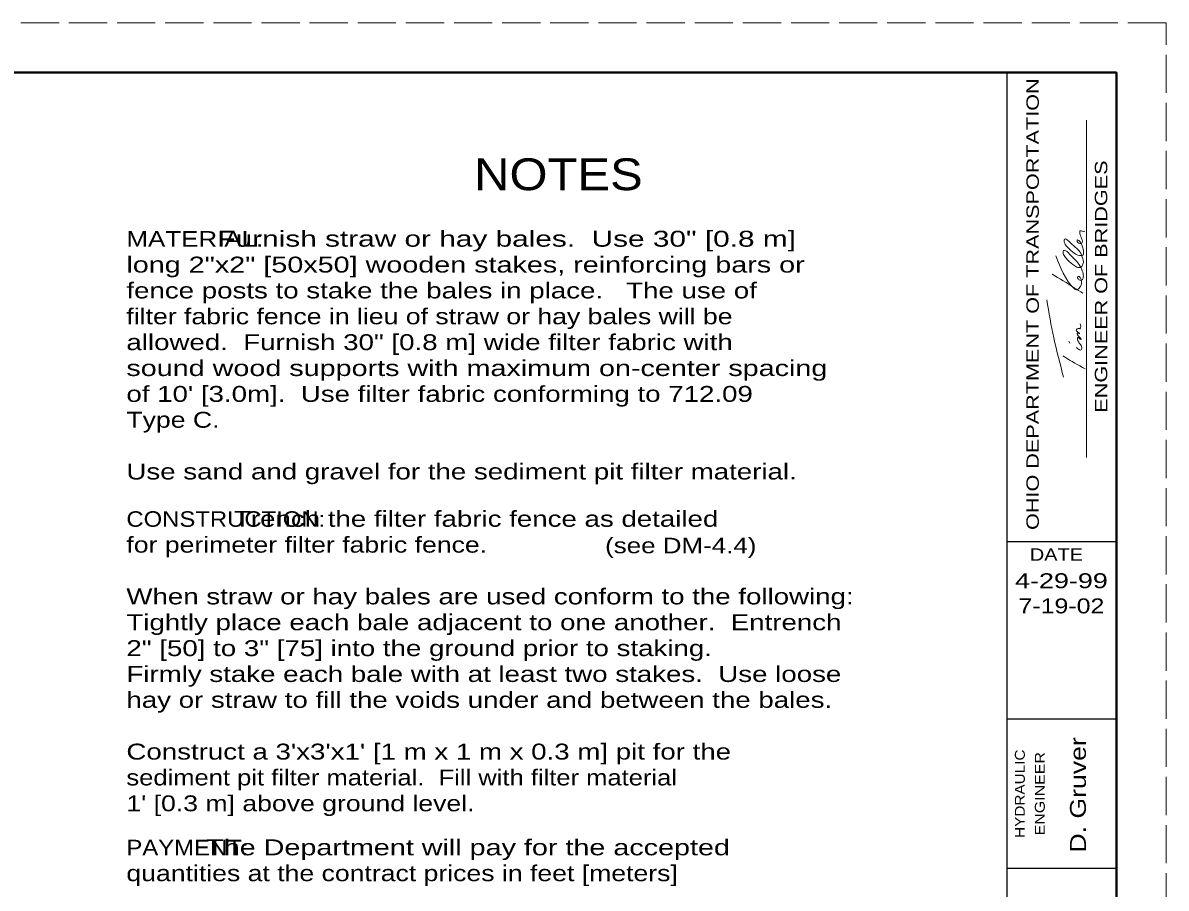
# Model space of a CAD drawing. Extents: x 1043.1 to 1101.1, y 672.4 to 716.4.
# Drawn here: x 1065.65 to 1077.14, y 707.7 to 716.4 of the extents above; entities that cross this region are included whole.
import ezdxf
from ezdxf.enums import TextEntityAlignment as Align

# ---------------------------------------------------------------- set-up
doc = ezdxf.new("R2010")
doc.units = 0
doc.header["$LTSCALE"] = 0.064
doc.linetypes.add('LONG_DASHED', pattern=[7.5, 6, -1.5])
doc.layers.add('1', color=7, linetype='Continuous', lineweight=13)

msp = doc.modelspace()

# ---------------------------------------------------------------- linework, layer by layer
at = {"layer": '1', "lineweight": 25}
for p, q in [((1045.14425, 715.89508), (1076.64425, 715.89508)), ((1075.54425, 694.89508), (1075.54425, 715.89508)), ((1076.64425, 715.89508), (1076.64425, 694.89508)), ((1076.64425, 711.17925), (1075.54425, 711.17925)), ((1076.64425, 709.39508), (1075.54425, 709.39508)), ((1076.64425, 707.89508), (1075.54425, 707.89508))]:
    msp.add_line(p, q, dxfattribs=at)
at = {"layer": '1', "lineweight": 40}
msp.add_line((1045.14425, 715.89508), (1076.64425, 715.89508), dxfattribs=at)
at = {"layer": '1'}
for p, q in [((1076.343, 712.02608), (1076.343, 715.41617)), ((1076.1755, 713.177), (1076.16533, 713.19625))]:
    msp.add_line(p, q, dxfattribs=at)
at = {"layer": '1', "linetype": 'LONG_DASHED'}
msp.add_lwpolyline([(1043.14425, 694.39508), (1077.14425, 694.39508), (1077.14425, 716.39508), (1043.14425, 716.39508)], close=True, dxfattribs=at)
at = {"layer": '1', "lineweight": 40}
msp.add_lwpolyline([(1045.14425, 715.89508), (1076.64425, 715.89508), (1076.64425, 694.89508), (1045.14425, 694.89508)], close=True, dxfattribs=at)
at = {"layer": '1'}
for points in [[(1076.03608, 714.05208), (1076.21925, 713.72375), (1076.23442, 713.71317), (1076.24458, 713.71317), (1076.2765, 713.73683), (1076.29158, 713.771), (1076.28658, 713.82225), (1076.26967, 713.84408), (1076.25617, 713.84408), (1076.25442, 713.83108), (1076.26458, 713.81592), (1076.27808, 713.8075), (1076.29317, 713.8075), (1076.30833, 713.82908), (1076.31175, 713.84842), (1076.3015, 713.90375), (1076.21925, 714.02417), (1076.17375, 714.06883), (1076.13683, 714.10342), (1076.11167, 714.10558), (1076.11342, 714.067), (1076.13858, 714.02825), (1076.20583, 713.96592), (1076.24792, 713.9405), (1076.28158, 713.936), (1076.30492, 713.962), (1076.31175, 713.99617), (1076.30667, 714.02192), (1076.2765, 714.09508), (1076.24625, 714.12708), (1076.18567, 714.1805), (1076.157, 714.20633), (1076.1235, 714.22158), (1076.12008, 714.19358), (1076.13017, 714.16775), (1076.18733, 714.10783), (1076.258, 714.06058), (1076.31, 714.06292), (1076.30833, 714.12058), (1076.2965, 714.1635), (1076.28317, 714.18925), (1076.273, 714.2), (1076.24958, 714.215), (1076.25133, 714.19792), (1076.28658, 714.17642), (1076.3015, 714.18717), (1076.28842, 714.24083), (1076.27983, 714.26875), (1076.2765, 714.28142), (1076.2765, 714.29425), (1076.2765, 714.30292), (1076.3015, 714.30075), (1076.32692, 714.30075)], [(1075.99725, 713.86983), (1076.221, 713.73233), (1076.30667, 713.67667)], [(1076.1135, 712.83283), (1076.01483, 713.22808), (1075.94358, 713.61042)], [(1076.24458, 713.13175), (1076.25283, 713.12108), (1076.29, 713.10817), (1076.29475, 713.14058), (1076.26967, 713.177), (1076.25442, 713.21325), (1076.25442, 713.2325), (1076.26967, 713.22625), (1076.27983, 713.21542), (1076.29, 713.21108), (1076.26633, 713.24325), (1076.25442, 713.25825), (1076.25133, 713.27558), (1076.27475, 713.269), (1076.26633, 713.27767), (1076.24117, 713.3055), (1076.25133, 713.32067), (1076.26808, 713.32267), (1076.2765, 713.32067), (1076.28658, 713.342), (1076.27983, 713.36992)], [(1076.32867, 712.91725), (1076.1235, 713.03725), (1076.10792, 713.04767)]]:
    msp.add_spline(points, degree=3, dxfattribs=at)

# ---------------------------------------------------------------- texts
for s, height, width, p in [('OHIO DEPARTMENT OF TRANSPORTATION', 0.125, 1.3, (1075.86417, 713.56733)), ('ENGINEER OF BRIDGES', 0.125, 1.3, (1076.5525, 713.74412)), ('D. Gruver', 0.16, 1.25, (1076.33758, 708.63433)), ('HYDRAULIC', 0.1, 1.15, (1075.72333, 708.64617)), ('ENGINEER', 0.1, 1.2, (1075.92425, 708.64621))]:
    msp.add_text(s, height=height, rotation=90, dxfattribs=dict(at, width=width)).set_placement(p, align=Align.CENTER)
for s, height, width, p in [('NOTES', 0.32, 1.15, (1071.03379, 714.71308)), ('DATE', 0.125, 1.2, (1076.04096, 710.98783)), ('4-29-99', 0.15, 1.35, (1076.09125, 710.71233)), ('7-19-02', 0.15, 1.25, (1076.09129, 710.45925))]:
    msp.add_text(s, height=height, dxfattribs=dict(at, width=width)).set_placement(p, align=Align.CENTER)
for s, height, width, p in [('MATERIAL:', 0.156, 1.25, (1066.68958, 714.14558)), ('           Furnish straw or hay bales.  Use 30" [0.8 m] ', 0.16, 1.4, (1066.68958, 714.14508)), ('long 2"x2" [50x50] wooden stakes, reinforcing bars or ', 0.16, 1.35, (1066.68958, 713.88508)), ('fence posts to stake the bales in place.   The use of ', 0.16, 1.3, (1066.68958, 713.62508)), ('filter fabric fence in lieu of straw or hay bales will be', 0.16, 1.25, (1066.68958, 713.36508)), ('allowed.  Furnish 30" [0.8 m] wide filter fabric with ', 0.16, 1.3, (1066.68958, 713.10508)), ('sound wood supports with maximum on-center spacing ', 0.16, 1.35, (1066.68958, 712.84508)), ("of 10' [3.0m].  Use filter fabric conforming to 712.09 ", 0.16, 1.3, (1066.68958, 712.58508)), ('Type C.', 0.16, 1.25, (1066.68958, 712.32508)), ('Use sand and gravel for the sediment pit filter material.', 0.16, 1.3, (1066.68958, 711.80508)), ('CONSTRUCTION:', 0.156, 1.15, (1066.68958, 711.3295)), ('              Trench the filter fabric fence as detailed', 0.16, 1.3, (1066.68958, 711.3295)), ('for perimeter filter fabric fence.', 0.16, 1.25, (1066.68958, 711.0695)), ('(see DM-4.4)', 0.156, 1.25, (1071.503, 711.06325)), ('When straw or hay bales are used conform to the following:', 0.16, 1.3, (1066.68958, 710.5495)), ('Tightly place each bale adjacent to one another.  Entrench', 0.16, 1.3, (1066.68958, 710.2895)), ('2" [50] to 3" [75] into the ground prior to staking.', 0.16, 1.3, (1066.68958, 710.0295)), ('Firmly stake each bale with at least two stakes.  Use loose', 0.16, 1.3, (1066.68958, 709.7695)), ('hay or straw to fill the voids under and between the bales.', 0.16, 1.3, (1066.68958, 709.5095)), ("Construct a 3'x3'x1' [1 m x 1 m x 0.3 m] pit for the", 0.16, 1.3, (1066.68958, 708.9895)), ('sediment pit filter material.  Fill with filter material', 0.16, 1.2, (1066.68958, 708.7295)), ("1' [0.3 m] above ground level.", 0.16, 1.25, (1066.68958, 708.4695)), ('PAYMENT:', 0.156, 1.15, (1066.68958, 708.027)), ('          The Department will pay for the accepted', 0.16, 1.35, (1066.68958, 708.027)), ('quantities at the contract prices in feet [meters]', 0.16, 1.25, (1066.68958, 707.767))]:
    msp.add_text(s, height=height, dxfattribs=dict(at, width=width)).set_placement(p)

doc.saveas('drawing.dxf')
